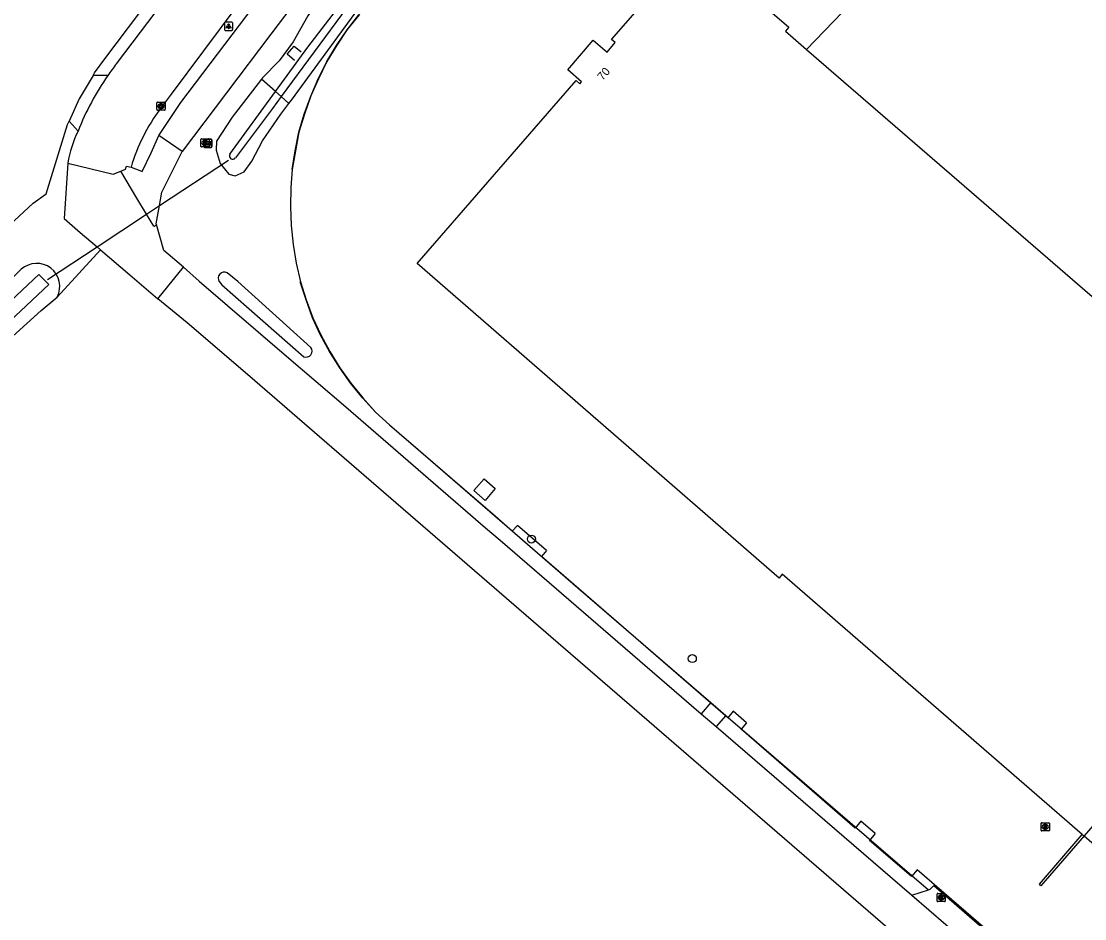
# Model space of a CAD drawing. Extents: x 156141 to 158132, y 385651 to 388399.
# Drawn here: x 156310.4 to 156440.2, y 387275.3 to 387384.8 of the extents above; entities that cross this region are included whole.
import ezdxf

# ---------------------------------------------------------------- set-up
doc = ezdxf.new("R2010")
doc.units = 0
for name, color, linetype in [('IMGEO_Berm_groen', 7, 'Continuous'), ('IMGEO_Berm_onverhard', 7, 'Continuous'), ('IMGEO_Boom', 7, 'Continuous'), ('IMGEO_Bouwland', 7, 'Continuous'), ('IMGEO_Brandkraan', 7, 'Continuous'), ('IMGEO_Duiker', 7, 'Continuous'), ('IMGEO_Fietspad_gesloten', 7, 'Continuous'), ('IMGEO_Fietspad_open', 7, 'Continuous'), ('IMGEO_Grasland_agrarisch', 7, 'Continuous'), ('IMGEO_Groenvoorziening', 7, 'Continuous'), ('IMGEO_Hek', 7, 'Continuous'), ('IMGEO_Kolk', 7, 'Continuous'), ('IMGEO_Lage_trafo', 7, 'Continuous'), ('IMGEO_Lichtpunt', 7, 'Continuous'), ('IMGEO_Muur', 7, 'Continuous'), ('IMGEO_Oever', 7, 'Continuous'), ('IMGEO_Pand', 7, 'Continuous'), ('IMGEO_Pand_nummerreeks', 7, 'Continuous'), ('IMGEO_Pand_overbouw', 7, 'Continuous'), ('IMGEO_Rijbaan_lokaal_gesloten', 7, 'Continuous'), ('IMGEO_Rijbaan_lokaal_open', 7, 'Continuous'), ('IMGEO_Rioolput', 7, 'Continuous'), ('IMGEO_Verklikker', 7, 'Continuous'), ('IMGEO_Voetpad_open', 7, 'Continuous'), ('IMGEO_Waterloop', 7, 'Continuous')]:
    doc.layers.add(name, color=color, linetype=linetype)

msp = doc.modelspace()

# ---------------------------------------------------------------- linework, layer by layer
at = {"layer": 'IMGEO_Berm_groen'}
msp.add_lwpolyline([(156319.17, 387378.21), (156319.34, 387378.5), (156320.57, 387380.23), (156330.62, 387393.58), (156329.74, 387394.29)], dxfattribs=at)
at = {"layer": 'IMGEO_Berm_onverhard'}
msp.add_lwpolyline([(156396.37, 387300.08), (156421.09, 387278.78)], dxfattribs=at)
at = {"layer": 'IMGEO_Boom'}
for centre in [(156372.64, 387321.6), (156392.28, 387307.01)]:
    msp.add_circle(centre, 0.489, dxfattribs=at)
at = {"layer": 'IMGEO_Bouwland'}
for points in [[(156314.77, 387351.15), (156320.06, 387356.92)], [(156265.52, 387305.48), (156271.96, 387311.16), (156281.29, 387320.18), (156289.11, 387327.51), (156297.87, 387335.47), (156303.17, 387340.79), (156312.8, 387349.49), (156314.77, 387351.15)]]:
    msp.add_lwpolyline(points, dxfattribs=at)
at = {"layer": 'IMGEO_Brandkraan'}
for p, q in [((156332.32, 387369.54), (156332.32, 387370.39)), ((156332.39, 387370.47), (156333.24, 387370.47)), ((156333.24, 387369.47), (156332.39, 387369.47)), ((156332.8, 387370.25), (156332.83, 387370.25)), ((156332.83, 387369.69), (156332.8, 387369.69)), ((156333.32, 387370.39), (156333.32, 387369.54))]:
    msp.add_line(p, q, dxfattribs=at)
for points in [[(156332.32, 387369.54), (156332.32, 387370.39)], [(156332.39, 387370.47), (156333.24, 387370.47)], [(156333.24, 387369.47), (156332.39, 387369.47)], [(156332.66, 387370.17), (156332.66, 387369.77), (156332.88, 387369.77)], [(156332.89, 387370.17), (156332.66, 387370.17)], [(156332.84, 387370.09), (156332.79, 387370.09), (156332.79, 387370.01)], [(156332.79, 387370.01), (156332.84, 387370.01)], [(156332.85, 387369.93), (156332.79, 387369.93), (156332.79, 387369.85)], [(156332.79, 387369.85), (156332.85, 387369.85)], [(156333.32, 387370.39), (156333.32, 387369.54)]]:
    msp.add_lwpolyline(points, dxfattribs=at)
for centre, radius, start, end in [((156332.39, 387370.39), 0.0765, 91.552, 178.448), ((156332.39, 387370.39), 0.0765, 91.552, 178.448), ((156332.39, 387369.54), 0.0765, 181.552, 268.448), ((156332.39, 387369.54), 0.0765, 181.552, 268.448), ((156332.84, 387370.05), 0.0379, 267.8285, 90.9355), ((156332.85, 387369.89), 0.0404, 269.8759, 90.5077), ((156332.88, 387370.02), 0.251, 268.6676, 293.5347), ((156332.9, 387370.02), 0.145, 59.4692, 91.5367), ((156332.92, 387370.07), 0.0922, 285.5137, 58.1501), ((156332.93, 387369.88), 0.105, 301.3115, 78.989), ((156333.24, 387370.39), 0.0765, 1.552, 88.448), ((156333.24, 387370.39), 0.0765, 1.552, 88.448), ((156333.24, 387369.54), 0.0765, 271.552, 358.448), ((156333.24, 387369.54), 0.0765, 271.552, 358.448)]:
    msp.add_arc(centre, radius, start, end, dxfattribs=at)
for centre, major_axis, ratio, start_param, end_param in [((156332.8, 387369.97), (-0.387, 0.002), 0.722429, 4.712389, 7.853982), ((156332.83, 387369.97), (-0.39, 0.002), 0.717154, 1.570796, 4.712389)]:
    msp.add_ellipse(centre, major_axis=major_axis, ratio=ratio, start_param=start_param, end_param=end_param, dxfattribs=at)
at = {"layer": 'IMGEO_Duiker'}
msp.add_lwpolyline([(156313.6, 387353.29), (156319.64, 387357.28), (156325.67, 387361.26), (156327.27, 387362.32), (156335.66, 387367.87)], dxfattribs=at)
at = {"layer": 'IMGEO_Fietspad_gesloten'}
for points in [[(156348.53, 387393.39), (156340.85, 387383.25), (156330.04, 387368.91)], [(156327.18, 387370.88), (156329.88, 387374.9), (156337.91, 387385.51), (156343.08, 387392.32)], [(156330.04, 387368.91), (156327.18, 387370.88)]]:
    msp.add_lwpolyline(points, dxfattribs=at)
at = {"layer": 'IMGEO_Fietspad_open'}
for points in [[(156323.79, 387366.99), (156324.87, 387366.61), (156325.16, 387366.49), (156326.23, 387368.77), (156327.18, 387370.88)], [(156326.89, 387360), (156326.87, 387360.09), (156327.27, 387362.32), (156327.55, 387363.95), (156330.04, 387368.91)]]:
    msp.add_lwpolyline(points, dxfattribs=at)
at = {"layer": 'IMGEO_Grasland_agrarisch'}
msp.add_lwpolyline([(156406.21, 387381.37), (156411.67, 387387.03), (156427.15, 387402.46), (156398.53, 387431.64)], dxfattribs=at)
at = {"layer": 'IMGEO_Groenvoorziening'}
for points in [[(156343.05, 387374.77), (156343.37, 387375.19), (156353.9, 387389.61), (156360.42, 387395.88), (156369.86, 387404.46), (156372.96, 387407.34), (156373.17, 387407.97), (156372.99, 387408.62), (156371.52, 387409.85), (156370.26, 387410.52), (156369.26, 387410.37), (156368.28, 387409.67), (156364.34, 387405.86), (156357.42, 387399.29), (156352.25, 387393.94), (156347.89, 387388.99), (156345.35, 387385.49), (156343.56, 387382.3), (156341.85, 387379.97), (156339.83, 387377.91), (156339.69, 387377.73)], [(156351.61, 387385.61), (156350.18, 387383.8), (156348.88, 387381.88), (156347.68, 387379.88), (156346.65, 387377.8), (156345.73, 387375.69), (156344.94, 387373.48), (156344.27, 387371.27), (156343.84, 387368.99), (156343.44, 387366.71), (156343.27, 387364.52), (156343.23, 387362.2), (156343.31, 387359.89), (156343.57, 387357.58), (156343.95, 387355.28), (156344.46, 387353.02), (156345.17, 387350.8), (156345.97, 387348.63), (156346.93, 387346.52), (156348.03, 387344.49), (156349.26, 387342.52), (156350.62, 387340.64), (156352.07, 387338.84), (156353.61, 387337.11), (156355.33, 387335.56), (156368.28, 387324.4), (156370.03, 387322.84), (156378.31, 387315.64), (156394.56, 387301.64)], [(156339.69, 387377.73), (156336.13, 387373.11), (156334.21, 387370.16), (156334.18, 387369.06), (156334.67, 387367.43), (156335.71, 387366.15), (156336.49, 387365.93), (156337.58, 387366.42), (156338.52, 387367.75), (156339.81, 387370.21), (156342.06, 387373.48), (156343.05, 387374.77)], [(156303.81, 387355.2), (156311.86, 387362.61), (156313.42, 387363.74), (156316.05, 387372.2), (156316.23, 387372.6)], [(156310.39, 387354.53), (156300.49, 387344.71), (156291.42, 387335.91), (156277.95, 387323.55), (156263.93, 387311.47)]]:
    msp.add_lwpolyline(points, dxfattribs=at)
msp.add_arc((156312.28, 387352.45), 2.81, 332.384, 132.1947, dxfattribs=at)
at = {"layer": 'IMGEO_Hek'}
for points in [[(156343.43, 387366.71), (156343.83, 387368.98), (156344.26, 387371.27), (156344.92, 387373.47), (156345.71, 387375.67), (156346.62, 387377.8), (156347.66, 387379.88), (156348.86, 387381.87), (156350.16, 387383.78), (156351.59, 387385.6), (156353.14, 387387.33), (156354.79, 387388.97), (156373.94, 387406.99), (156380.21, 387412.89), (156380.73, 387413.36)], [(156358.83, 387332.51), (156357.09, 387334.02), (156355.33, 387335.54), (156353.62, 387337.1), (156352.07, 387338.82), (156350.61, 387340.61), (156349.25, 387342.51), (156348.02, 387344.48), (156346.92, 387346.51), (156345.95, 387348.61), (156345.15, 387350.8), (156344.44, 387353)], [(156370.3, 387322.57), (156358.83, 387332.51)], [(156370.93, 387323.28), (156370.3, 387322.57)], [(156374.5, 387320.2), (156370.93, 387323.28)], [(156374.5, 387320.2), (156373.89, 387319.46)], [(156396.61, 387299.8), (156373.89, 387319.46)], [(156489.69, 387309.07), (156445.19, 387257.75), (156443.25, 387259.48), (156443.95, 387260.28), (156419.73, 387281.24), (156419.01, 387280.41)], [(156397.27, 387300.59), (156396.61, 387299.8)], [(156398.91, 387299.17), (156397.27, 387300.59)], [(156398.91, 387299.17), (156398.25, 387298.38)], [(156412.17, 387286.33), (156398.25, 387298.38)], [(156412.85, 387287.17), (156412.17, 387286.33)], [(156414.6, 387285.66), (156412.85, 387287.17)], [(156414.6, 387285.66), (156413.91, 387284.82)], [(156419.01, 387280.41), (156413.91, 387284.82)]]:
    msp.add_lwpolyline(points, dxfattribs=at)
at = {"layer": 'IMGEO_Kolk'}
for p, q in [((156326.95, 387374.02), (156326.95, 387374.87)), ((156327.02, 387374.95), (156327.87, 387374.95)), ((156327.43, 387374.73), (156327.46, 387374.73)), ((156327.95, 387374.87), (156327.95, 387374.02)), ((156327.87, 387373.95), (156327.02, 387373.95)), ((156327.46, 387374.17), (156327.43, 387374.17)), ((156422.15, 387277.42), (156422.15, 387278.27)), ((156422.22, 387278.35), (156423.08, 387278.35)), ((156423.08, 387277.35), (156422.22, 387277.35)), ((156422.66, 387277.57), (156422.63, 387277.57)), ((156422.64, 387278.13), (156422.66, 387278.13)), ((156423.15, 387278.27), (156423.15, 387277.42))]:
    msp.add_line(p, q, dxfattribs=at)
for points in [[(156326.95, 387374.02), (156326.95, 387374.87)], [(156327.02, 387374.95), (156327.87, 387374.95)], [(156327.27, 387374.65), (156327.39, 387374.65), (156327.39, 387374.5), (156327.52, 387374.65), (156327.68, 387374.65), (156327.54, 387374.5), (156327.69, 387374.25), (156327.54, 387374.25), (156327.45, 387374.41), (156327.39, 387374.34), (156327.39, 387374.25), (156327.27, 387374.25), (156327.27, 387374.65)], [(156327.95, 387374.87), (156327.95, 387374.02)], [(156327.87, 387373.95), (156327.02, 387373.95)], [(156422.15, 387277.42), (156422.15, 387278.27)], [(156422.22, 387278.35), (156423.08, 387278.35)], [(156423.08, 387277.35), (156422.22, 387277.35)], [(156422.47, 387278.05), (156422.59, 387278.05), (156422.59, 387277.89), (156422.72, 387278.05), (156422.89, 387278.05), (156422.74, 387277.9), (156422.89, 387277.65), (156422.74, 387277.65), (156422.66, 387277.81), (156422.59, 387277.74), (156422.59, 387277.65), (156422.47, 387277.65), (156422.47, 387278.05)], [(156423.15, 387278.27), (156423.15, 387277.42)]]:
    msp.add_lwpolyline(points, dxfattribs=at)
for centre, start, end in [((156327.02, 387374.87), 91.552, 178.448), ((156327.02, 387374.87), 91.552, 178.448), ((156327.87, 387374.87), 1.552, 88.448), ((156327.87, 387374.87), 1.552, 88.448), ((156327.02, 387374.02), 181.552, 268.448), ((156327.02, 387374.02), 181.552, 268.448), ((156327.87, 387374.02), 271.552, 358.448), ((156327.87, 387374.02), 271.552, 358.448), ((156422.23, 387278.27), 91.552, 178.448), ((156422.23, 387278.27), 91.552, 178.448), ((156422.23, 387277.42), 181.552, 268.448), ((156422.23, 387277.42), 181.552, 268.448), ((156423.07, 387278.27), 1.552, 88.448), ((156423.07, 387278.27), 1.552, 88.448), ((156423.07, 387277.42), 271.552, 358.448), ((156423.07, 387277.42), 271.552, 358.448)]:
    msp.add_arc(centre, 0.0765, start, end, dxfattribs=at)
for centre, major_axis, ratio, start_param, end_param in [((156327.43, 387374.45), (-0.387, 0.002), 0.722429, 4.712389, 7.853982), ((156327.46, 387374.45), (-0.39, 0.002), 0.717154, 1.570796, 4.712389), ((156422.64, 387277.85), (-0.387, 0.002), 0.722429, 4.712389, 7.853982), ((156422.66, 387277.85), (-0.39, 0.002), 0.717154, 1.570796, 4.712389)]:
    msp.add_ellipse(centre, major_axis=major_axis, ratio=ratio, start_param=start_param, end_param=end_param, dxfattribs=at)
at = {"layer": 'IMGEO_Lage_trafo'}
msp.add_lwpolyline([(156366.99, 387326.32), (156365.61, 387327.52), (156366.87, 387328.97), (156368.24, 387327.79), (156366.99, 387326.32)], dxfattribs=at)
at = {"layer": 'IMGEO_Lichtpunt'}
for p, q in [((156335.19, 387384.6), (156335.19, 387383.79)), ((156335.19, 387384.6), (156335.19, 387383.79)), ((156336.09, 387384.7), (156335.28, 387384.7)), ((156336.09, 387384.7), (156335.28, 387384.7)), ((156335.28, 387383.7), (156336.09, 387383.7)), ((156335.28, 387383.7), (156336.09, 387383.7)), ((156336.19, 387383.79), (156336.19, 387384.6)), ((156336.19, 387383.79), (156336.19, 387384.6))]:
    msp.add_line(p, q, dxfattribs=at)
for points in [[(156335.56, 387384.26), (156335.6, 387384.24), (156335.42, 387383.97), (156335.38, 387384), (156335.56, 387384.26)], [(156335.67, 387384.22), (156335.71, 387384.22), (156335.71, 387383.89), (156335.67, 387383.89), (156335.67, 387384.22)], [(156335.78, 387384.24), (156335.81, 387384.26), (156336, 387384), (156335.96, 387383.97), (156335.78, 387384.24)]]:
    msp.add_lwpolyline(points, dxfattribs=at)
msp.add_circle((156335.69, 387384.4), 0.0994, dxfattribs=at)
for centre, start, end in [((156335.28, 387384.6), 90, 180), ((156335.28, 387384.6), 90, 180), ((156335.28, 387383.79), 180, 270), ((156335.28, 387383.79), 180, 270), ((156336.09, 387384.6), 0, 90), ((156336.09, 387384.6), 0, 90), ((156336.09, 387383.79), 270, 0), ((156336.09, 387383.79), 270, 360)]:
    msp.add_arc(centre, 0.0946, start, end, dxfattribs=at)
at = {"layer": 'IMGEO_Muur'}
for points in [[(156343.74, 387380.04), (156342.85, 387380.79), (156343.71, 387381.77), (156344.55, 387381.06)], [(156440.09, 387285.36), (156434.82, 387279.28), (156434.63, 387279.46), (156439.86, 387285.56)]]:
    msp.add_lwpolyline(points, dxfattribs=at)
at = {"layer": 'IMGEO_Oever'}
for points in [[(156341.41, 387376.22), (156339.69, 387377.73)], [(156343.05, 387374.77), (156342.11, 387375.61)]]:
    msp.add_lwpolyline(points, dxfattribs=at)
at = {"layer": 'IMGEO_Pand'}
for points in [[(156439.86, 387285.56), (156403.26, 387317.31), (156402.86, 387316.84), (156358.72, 387355.23), (156378.1, 387377.58), (156378.55, 387377.18), (156378.77, 387377.43), (156377.09, 387378.89), (156380.2, 387382.51), (156381.87, 387381.05), (156382.88, 387382.21), (156382.42, 387382.6), (156392.45, 387394.11), (156404.05, 387384.08), (156403.64, 387383.6), (156404.58, 387382.78), (156406.21, 387381.37)], [(156406.21, 387381.37), (156481.08, 387316.61)], [(156447.73, 387278.73), (156457.03, 387289.46), (156449.39, 387296.09), (156440.09, 387285.36)], [(156439.86, 387285.56), (156440.09, 387285.36)]]:
    msp.add_lwpolyline(points, dxfattribs=at)
at = {"layer": 'IMGEO_Pand_overbouw'}
msp.add_lwpolyline([(156457.03, 387289.46), (156449.39, 387296.09), (156440.09, 387285.36), (156447.73, 387278.73)], close=True, dxfattribs=at)
at = {"layer": 'IMGEO_Rijbaan_lokaal_gesloten'}
for points in [[(156336.54, 387398.94), (156330.64, 387391.1), (156321.99, 387379.62)], [(156327.38, 387374.11), (156328.71, 387375.91), (156336.62, 387386.5), (156341.15, 387392.56)], [(156316.08, 387367.49), (156321.62, 387366.13), (156322.53, 387366.52)], [(156322.53, 387366.52), (156323.12, 387366.76), (156323.24, 387367.13), (156323.79, 387366.99)], [(156327.05, 387350.93), (156330.17, 387354.8)], [(156330.17, 387354.8), (156332.12, 387353.09), (156342.75, 387343.95), (156350, 387337.73), (156367.05, 387322.99), (156368.83, 387321.45), (156393.38, 387300.27)], [(156420.04, 387270.72), (156346.77, 387334.07), (156338.29, 387341.43), (156330.65, 387347.98), (156327.05, 387350.93)], [(156393.38, 387300.27), (156395.19, 387298.72)], [(156395.19, 387298.72), (156419.06, 387278.12)], [(156419.06, 387278.12), (156441.89, 387258.43)]]:
    msp.add_lwpolyline(points, dxfattribs=at)
for centre, radius, start, end in [((156348.17, 387359.34), 33.11, 142.2357, 145.295), ((156349.37, 387358.64), 34.5, 145.4802, 158.2776), ((156344.44, 387361.05), 21.49, 142.5611, 163.9424), ((156329.71, 387365.32), 13.81, 153.8138, 170.9378)]:
    msp.add_arc(centre, radius, start, end, dxfattribs=at)
at = {"layer": 'IMGEO_Rijbaan_lokaal_open'}
for points in [[(156316.08, 387367.49), (156315.64, 387360.73), (156317.59, 387359.04), (156319.64, 387357.28), (156320.06, 387356.92)], [(156326.89, 387360), (156326.66, 387359.75), (156326.59, 387359.8), (156326.55, 387359.79), (156325.67, 387361.26), (156324.5, 387363.22), (156322.53, 387366.52)], [(156330.17, 387354.8), (156327.77, 387356.84), (156326.89, 387360)], [(156320.06, 387356.92), (156323.64, 387353.85), (156327.05, 387350.93)], [(156419.06, 387278.12), (156421.09, 387278.78)], [(156421.09, 387278.78), (156421.32, 387278.85), (156421.75, 387279.31), (156442.58, 387261.23), (156442.21, 387260.75), (156442.18, 387260.52)]]:
    msp.add_lwpolyline(points, dxfattribs=at)
at = {"layer": 'IMGEO_Rioolput'}
for p, q in [((156434.85, 387286.05), (156434.85, 387286.91)), ((156434.92, 387286.98), (156435.77, 387286.98)), ((156435.33, 387286.76), (156435.36, 387286.76)), ((156435.85, 387286.91), (156435.85, 387286.05)), ((156435.77, 387285.98), (156434.92, 387285.98)), ((156435.36, 387286.2), (156435.33, 387286.2))]:
    msp.add_line(p, q, dxfattribs=at)
for points in [[(156434.85, 387286.05), (156434.85, 387286.91)], [(156434.92, 387286.98), (156435.77, 387286.98)], [(156435.44, 387286.68), (156435.18, 387286.68), (156435.18, 387286.28)], [(156435.18, 387286.28), (156435.31, 387286.28), (156435.31, 387286.44), (156435.32, 387286.44)], [(156435.36, 387286.6), (156435.31, 387286.6), (156435.31, 387286.52)], [(156435.31, 387286.52), (156435.36, 387286.52)], [(156435.36, 387286.41), (156435.44, 387286.28), (156435.58, 387286.28), (156435.51, 387286.41)], [(156435.85, 387286.91), (156435.85, 387286.05)], [(156435.77, 387285.98), (156434.92, 387285.98)]]:
    msp.add_lwpolyline(points, dxfattribs=at)
for centre, radius, start, end in [((156434.92, 387286.9), 0.0765, 91.552, 178.448), ((156434.92, 387286.9), 0.0765, 91.552, 178.448), ((156435.32, 387286.39), 0.0533, 26.0293, 88.6989), ((156435.37, 387286.5), 0.0964, 77.0061, 93.1865), ((156435.34, 387286.71), 0.19, 274.7715, 282.9687), ((156435.38, 387286.56), 0.0378, 276.6634, 79.6772), ((156435.43, 387286.57), 0.109, 350.3612, 89.416), ((156435.43, 387286.57), 0.112, 277.5842, 350.9817), ((156435.42, 387286.35), 0.108, 29.5134, 73.7905), ((156435.77, 387286.9), 0.0765, 1.552, 88.448), ((156435.77, 387286.9), 0.0765, 1.552, 88.448), ((156434.92, 387286.05), 0.0765, 181.552, 268.448), ((156434.92, 387286.05), 0.0765, 181.552, 268.448), ((156435.77, 387286.05), 0.0765, 271.552, 358.448), ((156435.77, 387286.05), 0.0765, 271.552, 358.448)]:
    msp.add_arc(centre, radius, start, end, dxfattribs=at)
for centre, major_axis, ratio, start_param, end_param in [((156435.33, 387286.48), (-0.387, 0.002), 0.722429, 4.712389, 7.853982), ((156435.36, 387286.48), (-0.39, 0.002), 0.717154, 1.570796, 4.712389)]:
    msp.add_ellipse(centre, major_axis=major_axis, ratio=ratio, start_param=start_param, end_param=end_param, dxfattribs=at)
at = {"layer": 'IMGEO_Verklikker'}
for p, q in [((156332.67, 387369.52), (156332.67, 387370.32)), ((156332.67, 387370.32), (156332.67, 387369.52)), ((156332.77, 387370.42), (156333.56, 387370.42)), ((156333.56, 387370.42), (156332.77, 387370.42)), ((156333.56, 387369.42), (156332.77, 387369.42)), ((156332.77, 387369.42), (156333.56, 387369.42)), ((156333.66, 387370.32), (156333.66, 387369.52)), ((156333.66, 387369.52), (156333.66, 387370.32))]:
    msp.add_line(p, q, dxfattribs=at)
for points in [[(156332.77, 387370.15), (156333.56, 387370.15), (156333.56, 387369.69), (156332.77, 387369.69), (156332.77, 387370.15)], [(156332.83, 387370.09), (156332.83, 387369.75), (156333.49, 387369.75), (156333.49, 387370.09), (156332.83, 387370.09)]]:
    msp.add_lwpolyline(points, dxfattribs=at)
for centre, start, end in [((156332.77, 387370.32), 90, 180), ((156332.77, 387370.32), 90, 180), ((156332.77, 387369.52), 180, 270), ((156332.77, 387369.52), 180, 270), ((156333.56, 387370.32), 0, 90), ((156333.56, 387370.32), 360, 90), ((156333.56, 387369.52), 270, 0), ((156333.56, 387369.52), 270, 0)]:
    msp.add_arc(centre, 0.1, start, end, dxfattribs=at)
at = {"layer": 'IMGEO_Voetpad_open'}
for points in [[(156319.17, 387378.21), (156317.47, 387375.33), (156316.23, 387372.6)], [(156320.95, 387378.2), (156319.17, 387378.21)], [(156316.23, 387372.6), (156317.32, 387371.41)], [(156394.56, 387301.64), (156393.38, 387300.27)], [(156394.56, 387301.64), (156396.37, 387300.08)], [(156396.37, 387300.08), (156395.19, 387298.72)]]:
    msp.add_lwpolyline(points, dxfattribs=at)
at = {"layer": 'IMGEO_Waterloop'}
for points in [[(156341.41, 387376.22), (156345.35, 387381.65), (156349.68, 387387.25), (156353.33, 387391.41), (156357.32, 387395.3), (156363.85, 387401.21), (156370.75, 387408.67), (156371.47, 387408.09), (156371.01, 387407.49), (156358.77, 387395.67), (156356.19, 387393.33), (156353.8, 387390.89), (156350.15, 387386.55), (156342.11, 387375.61)], [(156335.86, 387368.57), (156341.41, 387376.22)], [(156341.41, 387376.22), (156342.11, 387375.61)], [(156342.11, 387375.61), (156341.03, 387374.15), (156336.52, 387368.13)], [(156264.61, 387308.87), (156312.54, 387353.89), (156313.76, 387352.67), (156265.16, 387306.98)], [(156345.73, 387345), (156336.81, 387353.06), (156335.52, 387354.1)], [(156334.55, 387353.03), (156334.88, 387352.63)], [(156334.88, 387352.63), (156344.87, 387343.84)]]:
    msp.add_lwpolyline(points, dxfattribs=at)
for centre, radius, start, end in [((156336.19, 387368.36), 0.393, 148.8309, 324.5165), ((156335.16, 387353.46), 0.742, 60.419, 215.2359), ((156345.11, 387344.56), 0.761, 251.3521, 35.8725)]:
    msp.add_arc(centre, radius, start, end, dxfattribs=at)

# ---------------------------------------------------------------- texts
at = {"layer": 'IMGEO_Pand_nummerreeks'}
msp.add_text('70', height=1, rotation=49.1025, dxfattribs=at).set_placement((156381.35, 387377.51))

doc.saveas('drawing.dxf')
